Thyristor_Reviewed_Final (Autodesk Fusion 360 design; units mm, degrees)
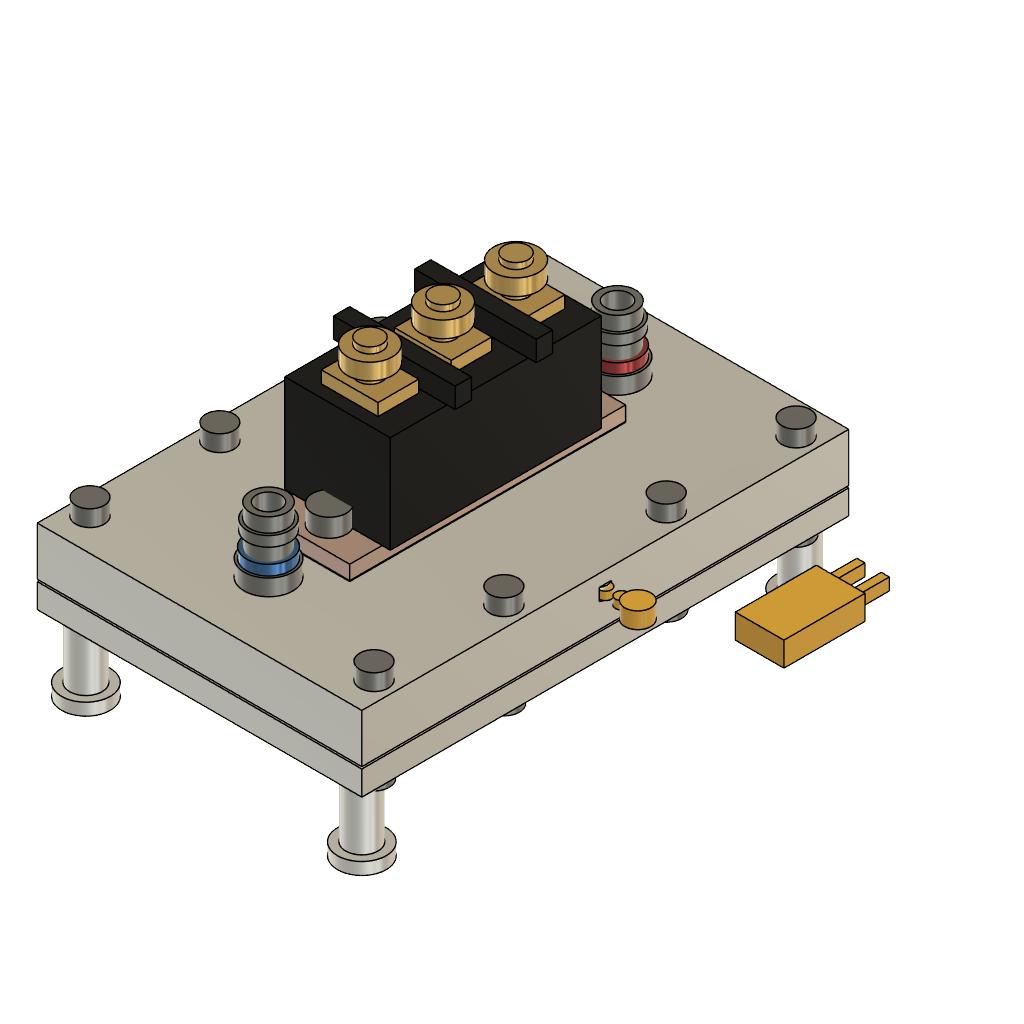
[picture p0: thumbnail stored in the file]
part number: 2026-11-02-01-28-30-721
part number: 2026-11-02-02-59-40-221
part number: 2026-11-02-02-59-43-084
part number: 2026-11-02-02-59-43-519
part number: 2026-11-02-02-59-44-128
part number: 2026-11-02-02-59-44-602
part number: 2026-11-02-02-59-44-987
part number: 2026-11-02-02-59-46-241
part number: 2026-11-02-02-59-47-034
part number: 2026-11-02-02-59-47-858
part number: 2026-11-02-02-59-48-789
part number: 2026-11-02-02-59-49-745
part number: 2026-11-02-02-59-54-096
part number: 2026-11-02-02-59-54-882
part number: 2026-11-02-02-59-56-951
part number: 2026-11-02-03-00-06-820
part number: 2026-11-02-03-00-18-161
part number: 2026-11-02-03-00-22-757
work_plane "WorkPlane1" AlongDistance 0 ExtraOffset 0
sketch "Cold plate stock sketch" plane through (0, 0, 0) normal (0, 0, 1) x axis (1, 0, 0)
  line L1 (80, 0) -> (0, 0)
  line L2 (80, 120) -> (80, 0)
  line L3 (0, 120) -> (80, 120)
  line L4 (0, 0) -> (0, 120)
extrude "Extrude1" new body sketch "Cold plate stock sketch" along normal blind 12
work_plane "WorkPlane2" AlongDistance 0 ExtraOffset 0
sketch "16 Mini-Channels | 2 x 5 x 70 mm sketch" plane through (0, 0, 0) normal (0, 0, 1) x axis (1, 0, 0)
  line L1 (14.75, 25) -> (12.75, 25)
  line L2 (14.75, 95) -> (14.75, 25)
  line L3 (12.75, 95) -> (14.75, 95)
  line L4 (12.75, 25) -> (12.75, 95)
  line L5 (18.25, 25) -> (16.25, 25)
  line L6 (18.25, 95) -> (18.25, 25)
  line L7 (16.25, 95) -> (18.25, 95)
  line L8 (16.25, 25) -> (16.25, 95)
  line L9 (21.75, 25) -> (19.75, 25)
  line L10 (21.75, 95) -> (21.75, 25)
  line L11 (19.75, 95) -> (21.75, 95)
  line L12 (19.75, 25) -> (19.75, 95)
  line L13 (25.25, 25) -> (23.25, 25)
  line L14 (25.25, 95) -> (25.25, 25)
  line L15 (23.25, 95) -> (25.25, 95)
  line L16 (23.25, 25) -> (23.25, 95)
  line L17 (28.75, 25) -> (26.75, 25)
  line L18 (28.75, 95) -> (28.75, 25)
  line L19 (26.75, 95) -> (28.75, 95)
  line L20 (26.75, 25) -> (26.75, 95)
  line L21 (32.25, 25) -> (30.25, 25)
  line L22 (32.25, 95) -> (32.25, 25)
  line L23 (30.25, 95) -> (32.25, 95)
  line L24 (30.25, 25) -> (30.25, 95)
  line L25 (35.75, 25) -> (33.75, 25)
  line L26 (35.75, 95) -> (35.75, 25)
  line L27 (33.75, 95) -> (35.75, 95)
  line L28 (33.75, 25) -> (33.75, 95)
  line L29 (39.25, 25) -> (37.25, 25)
  line L30 (39.25, 95) -> (39.25, 25)
  line L31 (37.25, 95) -> (39.25, 95)
  line L32 (37.25, 25) -> (37.25, 95)
  line L33 (42.75, 25) -> (40.75, 25)
  line L34 (42.75, 95) -> (42.75, 25)
  line L35 (40.75, 95) -> (42.75, 95)
  line L36 (40.75, 25) -> (40.75, 95)
  line L37 (46.25, 25) -> (44.25, 25)
  line L38 (46.25, 95) -> (46.25, 25)
  line L39 (44.25, 95) -> (46.25, 95)
  line L40 (44.25, 25) -> (44.25, 95)
  line L41 (49.75, 25) -> (47.75, 25)
  line L42 (49.75, 95) -> (49.75, 25)
  line L43 (47.75, 95) -> (49.75, 95)
  line L44 (47.75, 25) -> (47.75, 95)
  line L45 (53.25, 25) -> (51.25, 25)
  line L46 (53.25, 95) -> (53.25, 25)
  line L47 (51.25, 95) -> (53.25, 95)
  line L48 (51.25, 25) -> (51.25, 95)
  line L49 (56.75, 25) -> (54.75, 25)
  line L50 (56.75, 95) -> (56.75, 25)
  line L51 (54.75, 95) -> (56.75, 95)
  line L52 (54.75, 25) -> (54.75, 95)
  line L53 (60.25, 25) -> (58.25, 25)
  line L54 (60.25, 95) -> (60.25, 25)
  line L55 (58.25, 95) -> (60.25, 95)
  line L56 (58.25, 25) -> (58.25, 95)
  line L57 (63.75, 25) -> (61.75, 25)
  line L58 (63.75, 95) -> (63.75, 25)
  line L59 (61.75, 95) -> (63.75, 95)
  line L60 (61.75, 25) -> (61.75, 95)
  line L61 (67.25, 25) -> (65.25, 25)
  line L62 (67.25, 95) -> (67.25, 25)
  line L63 (65.25, 95) -> (67.25, 95)
  line L64 (65.25, 25) -> (65.25, 95)
extrude "Extrude2" cut sketch "16 Mini-Channels | 2 x 5 x 70 mm sketch" along normal blind 5
work_plane "WorkPlane3" AlongDistance 0 ExtraOffset 0
sketch "Headers sketch" plane through (0, 0, 0) normal (0, 0, 1) x axis (1, 0, 0)
  line L1 (70, 10) -> (10, 10)
  line L2 (70, 25) -> (70, 10)
  line L3 (10, 25) -> (70, 25)
  line L4 (10, 10) -> (10, 25)
  line L5 (70, 95) -> (10, 95)
  line L6 (70, 110) -> (70, 95)
  line L7 (10, 110) -> (70, 110)
  line L8 (10, 95) -> (10, 110)
extrude "Extrude3" cut sketch "Headers sketch" along normal blind 5
work_plane "WorkPlane4" AlongDistance 0 ExtraOffset 0
sketch "Boundary-layer breaks sketch" plane through (0, 0, 0) normal (0, 0, 1) x axis (1, 0, 0)
  line L1 (16.3, 42) -> (14.7, 42)
  line L2 (16.3, 44.5) -> (16.3, 42)
  line L3 (14.7, 44.5) -> (16.3, 44.5)
  line L4 (14.7, 42) -> (14.7, 44.5)
  line L5 (16.3, 68) -> (14.7, 68)
  line L6 (16.3, 70.5) -> (16.3, 68)
  line L7 (14.7, 70.5) -> (16.3, 70.5)
  line L8 (14.7, 68) -> (14.7, 70.5)
  line L9 (19.8, 52) -> (18.2, 52)
  line L10 (19.8, 54.5) -> (19.8, 52)
  line L11 (18.2, 54.5) -> (19.8, 54.5)
  line L12 (18.2, 52) -> (18.2, 54.5)
  line L13 (19.8, 78) -> (18.2, 78)
  line L14 (19.8, 80.5) -> (19.8, 78)
  line L15 (18.2, 80.5) -> (19.8, 80.5)
  line L16 (18.2, 78) -> (18.2, 80.5)
  line L17 (23.3, 42) -> (21.7, 42)
  line L18 (23.3, 44.5) -> (23.3, 42)
  line L19 (21.7, 44.5) -> (23.3, 44.5)
  line L20 (21.7, 42) -> (21.7, 44.5)
  line L21 (23.3, 68) -> (21.7, 68)
  line L22 (23.3, 70.5) -> (23.3, 68)
  line L23 (21.7, 70.5) -> (23.3, 70.5)
  line L24 (21.7, 68) -> (21.7, 70.5)
  line L25 (26.8, 52) -> (25.2, 52)
  line L26 (26.8, 54.5) -> (26.8, 52)
  line L27 (25.2, 54.5) -> (26.8, 54.5)
  line L28 (25.2, 52) -> (25.2, 54.5)
  line L29 (26.8, 78) -> (25.2, 78)
  line L30 (26.8, 80.5) -> (26.8, 78)
  line L31 (25.2, 80.5) -> (26.8, 80.5)
  line L32 (25.2, 78) -> (25.2, 80.5)
  line L33 (30.3, 42) -> (28.7, 42)
  line L34 (30.3, 44.5) -> (30.3, 42)
  line L35 (28.7, 44.5) -> (30.3, 44.5)
  line L36 (28.7, 42) -> (28.7, 44.5)
  line L37 (30.3, 68) -> (28.7, 68)
  line L38 (30.3, 70.5) -> (30.3, 68)
  line L39 (28.7, 70.5) -> (30.3, 70.5)
  line L40 (28.7, 68) -> (28.7, 70.5)
  line L41 (33.8, 52) -> (32.2, 52)
  line L42 (33.8, 54.5) -> (33.8, 52)
  line L43 (32.2, 54.5) -> (33.8, 54.5)
  line L44 (32.2, 52) -> (32.2, 54.5)
  line L45 (33.8, 78) -> (32.2, 78)
  line L46 (33.8, 80.5) -> (33.8, 78)
  line L47 (32.2, 80.5) -> (33.8, 80.5)
  line L48 (32.2, 78) -> (32.2, 80.5)
  line L49 (37.3, 42) -> (35.7, 42)
  line L50 (37.3, 44.5) -> (37.3, 42)
  line L51 (35.7, 44.5) -> (37.3, 44.5)
  line L52 (35.7, 42) -> (35.7, 44.5)
  line L53 (37.3, 68) -> (35.7, 68)
  line L54 (37.3, 70.5) -> (37.3, 68)
  line L55 (35.7, 70.5) -> (37.3, 70.5)
  line L56 (35.7, 68) -> (35.7, 70.5)
  line L57 (40.8, 52) -> (39.2, 52)
  line L58 (40.8, 54.5) -> (40.8, 52)
  line L59 (39.2, 54.5) -> (40.8, 54.5)
  line L60 (39.2, 52) -> (39.2, 54.5)
  line L61 (40.8, 78) -> (39.2, 78)
  line L62 (40.8, 80.5) -> (40.8, 78)
  line L63 (39.2, 80.5) -> (40.8, 80.5)
  line L64 (39.2, 78) -> (39.2, 80.5)
  line L65 (44.3, 42) -> (42.7, 42)
  line L66 (44.3, 44.5) -> (44.3, 42)
  line L67 (42.7, 44.5) -> (44.3, 44.5)
  line L68 (42.7, 42) -> (42.7, 44.5)
  line L69 (44.3, 68) -> (42.7, 68)
  line L70 (44.3, 70.5) -> (44.3, 68)
  line L71 (42.7, 70.5) -> (44.3, 70.5)
  line L72 (42.7, 68) -> (42.7, 70.5)
  line L73 (47.8, 52) -> (46.2, 52)
  line L74 (47.8, 54.5) -> (47.8, 52)
  line L75 (46.2, 54.5) -> (47.8, 54.5)
  line L76 (46.2, 52) -> (46.2, 54.5)
  line L77 (47.8, 78) -> (46.2, 78)
  line L78 (47.8, 80.5) -> (47.8, 78)
  line L79 (46.2, 80.5) -> (47.8, 80.5)
  line L80 (46.2, 78) -> (46.2, 80.5)
  line L81 (51.3, 42) -> (49.7, 42)
  line L82 (51.3, 44.5) -> (51.3, 42)
  line L83 (49.7, 44.5) -> (51.3, 44.5)
  line L84 (49.7, 42) -> (49.7, 44.5)
  line L85 (51.3, 68) -> (49.7, 68)
  line L86 (51.3, 70.5) -> (51.3, 68)
  line L87 (49.7, 70.5) -> (51.3, 70.5)
  line L88 (49.7, 68) -> (49.7, 70.5)
  line L89 (54.8, 52) -> (53.2, 52)
  line L90 (54.8, 54.5) -> (54.8, 52)
  line L91 (53.2, 54.5) -> (54.8, 54.5)
  line L92 (53.2, 52) -> (53.2, 54.5)
  line L93 (54.8, 78) -> (53.2, 78)
  line L94 (54.8, 80.5) -> (54.8, 78)
  line L95 (53.2, 80.5) -> (54.8, 80.5)
  line L96 (53.2, 78) -> (53.2, 80.5)
  line L97 (58.3, 42) -> (56.7, 42)
  line L98 (58.3, 44.5) -> (58.3, 42)
  line L99 (56.7, 44.5) -> (58.3, 44.5)
  line L100 (56.7, 42) -> (56.7, 44.5)
  line L101 (58.3, 68) -> (56.7, 68)
  line L102 (58.3, 70.5) -> (58.3, 68)
  line L103 (56.7, 70.5) -> (58.3, 70.5)
  line L104 (56.7, 68) -> (56.7, 70.5)
  line L105 (61.8, 52) -> (60.2, 52)
  line L106 (61.8, 54.5) -> (61.8, 52)
  line L107 (60.2, 54.5) -> (61.8, 54.5)
  line L108 (60.2, 52) -> (60.2, 54.5)
  line L109 (61.8, 78) -> (60.2, 78)
  line L110 (61.8, 80.5) -> (61.8, 78)
  line L111 (60.2, 80.5) -> (61.8, 80.5)
  line L112 (60.2, 78) -> (60.2, 80.5)
  line L113 (65.3, 42) -> (63.7, 42)
  line L114 (65.3, 44.5) -> (65.3, 42)
  line L115 (63.7, 44.5) -> (65.3, 44.5)
  line L116 (63.7, 42) -> (63.7, 44.5)
  line L117 (65.3, 68) -> (63.7, 68)
  line L118 (65.3, 70.5) -> (65.3, 68)
  line L119 (63.7, 70.5) -> (65.3, 70.5)
  line L120 (63.7, 68) -> (63.7, 70.5)
extrude "Extrude4" cut sketch "Boundary-layer breaks sketch" along normal blind 5
work_plane "WorkPlane5" AlongDistance 0 ExtraOffset 0
sketch "Gasket groove 1 sketch" plane through (0, 0, 0) normal (0, 0, 1) x axis (1, 0, 0)
  line L1 (73, 7) -> (7, 7)
  line L2 (73, 9) -> (73, 7)
  line L3 (7, 9) -> (73, 9)
  line L4 (7, 7) -> (7, 9)
extrude "Extrude5" cut sketch "Gasket groove 1 sketch" along normal blind 0.5
work_plane "WorkPlane6" AlongDistance 0 ExtraOffset 0
sketch "Gasket groove 2 sketch" plane through (0, 0, 0) normal (0, 0, 1) x axis (1, 0, 0)
  line L1 (73, 111) -> (7, 111)
  line L2 (73, 113) -> (73, 111)
  line L3 (7, 113) -> (73, 113)
  line L4 (7, 111) -> (7, 113)
extrude "Extrude6" cut sketch "Gasket groove 2 sketch" along normal blind 0.5
work_plane "WorkPlane7" AlongDistance 0 ExtraOffset 0
sketch "Gasket groove 3 sketch" plane through (0, 0, 0) normal (0, 0, 1) x axis (1, 0, 0)
  line L1 (9, 9) -> (7, 9)
  line L2 (9, 111) -> (9, 9)
  line L3 (7, 111) -> (9, 111)
  line L4 (7, 9) -> (7, 111)
extrude "Extrude7" cut sketch "Gasket groove 3 sketch" along normal blind 0.5
work_plane "WorkPlane8" AlongDistance 0 ExtraOffset 0
sketch "Gasket groove 4 sketch" plane through (0, 0, 0) normal (0, 0, 1) x axis (1, 0, 0)
  line L1 (73, 9) -> (71, 9)
  line L2 (73, 111) -> (73, 9)
  line L3 (71, 111) -> (73, 111)
  line L4 (71, 9) -> (71, 111)
extrude "Extrude8" cut sketch "Gasket groove 4 sketch" along normal blind 0.5
work_plane "WorkPlane9" AlongDistance 12 ExtraOffset 0
sketch "Fluid port through-bores sketch" plane through (0, 0, 12) normal (0, 0, 1) x axis (1, 0, 0)
  circle C1 centre (40, 17) radius 3
  circle C2 centre (40, 103) radius 3
extrude "Extrude9" cut sketch "Fluid port through-bores sketch" against normal blind 7 (magnitude of "-( 7 mm )")
work_plane "WorkPlane10" AlongDistance 12 ExtraOffset 0
sketch "Cover bolt holes sketch" plane through (0, 0, 12) normal (0, 0, 1) x axis (1, 0, 0)
  circle C1 centre (5, 8) radius 2.2
  circle C2 centre (75, 8) radius 2.2
  circle C3 centre (5, 40) radius 2.2
  circle C4 centre (75, 40) radius 2.2
  circle C5 centre (5, 80) radius 2.2
  circle C6 centre (75, 80) radius 2.2
  circle C7 centre (5, 112) radius 2.2
  circle C8 centre (75, 112) radius 2.2
extrude "Extrude10" cut sketch "Cover bolt holes sketch" against normal blind 12 (magnitude of "-( 12 mm )")
work_plane "WorkPlane11" AlongDistance 12 ExtraOffset 0
sketch "SCR M5 tapped holes sketch" plane through (0, 0, 12) normal (0, 0, 1) x axis (1, 0, 0)
  circle C1 centre (40, 32) radius 2.1
  circle C2 centre (40, 88) radius 2.1
extrude "Extrude11" cut sketch "SCR M5 tapped holes sketch" along normal blind 4
work_plane "WorkPlane12" AlongDistance 6 ExtraOffset 0
sketch "Thermowell entry boss sketch" plane through (0, 0, 6) normal (0, 0, 1) x axis (1, 0, 0)
  circle C1 centre (78, 60) radius 2.5
extrude "Extrude12" add sketch "Thermowell entry boss sketch" along normal blind 3
work_plane "WorkPlane1" AlongDistance 0 ExtraOffset 0
sketch "Gasket blank sketch" plane through (0, 0, 0) normal (0, 0, 1) x axis (1, 0, 0)
  line L1 (73, 7) -> (7, 7)
  line L2 (73, 113) -> (73, 7)
  line L3 (7, 113) -> (73, 113)
  line L4 (7, 7) -> (7, 113)
extrude "Extrude1" new body sketch "Gasket blank sketch" against normal blind 0.5 (magnitude of "-( 0.5 mm )")
work_plane "WorkPlane2" AlongDistance 0 ExtraOffset 0
sketch "Gasket fluid aperture sketch" plane through (0, 0, 0) normal (0, 0, 1) x axis (1, 0, 0)
  line L1 (71, 9) -> (9, 9)
  line L2 (71, 111) -> (71, 9)
  line L3 (9, 111) -> (71, 111)
  line L4 (9, 9) -> (9, 111)
extrude "Extrude2" cut sketch "Gasket fluid aperture sketch" against normal blind 0.5 (magnitude of "-( 0.5 mm )")
work_plane "WorkPlane1" AlongDistance -0.5 ExtraOffset 0
sketch "Bottom cover slab sketch" plane through (0, 0, -0.5) normal (0, 0, 1) x axis (1, 0, 0)
  line L1 (80, 0) -> (0, 0)
  line L2 (80, 120) -> (80, 0)
  line L3 (0, 120) -> (80, 120)
  line L4 (0, 0) -> (0, 120)
extrude "Extrude1" new body sketch "Bottom cover slab sketch" against normal blind 6 (magnitude of "-( 6.0 mm )")
work_plane "WorkPlane2" AlongDistance -0.5 ExtraOffset 0
sketch "Cover bolt holes sketch" plane through (0, 0, -0.5) normal (0, 0, 1) x axis (1, 0, 0)
  circle C1 centre (5, 8) radius 2.2
  circle C2 centre (75, 8) radius 2.2
  circle C3 centre (5, 40) radius 2.2
  circle C4 centre (75, 40) radius 2.2
  circle C5 centre (5, 80) radius 2.2
  circle C6 centre (75, 80) radius 2.2
  circle C7 centre (5, 112) radius 2.2
  circle C8 centre (75, 112) radius 2.2
extrude "Extrude2" cut sketch "Cover bolt holes sketch" against normal blind 6 (magnitude of "-( 6.0 mm )")
work_plane "WorkPlane1" AlongDistance 12 ExtraOffset 0
sketch "Hex collar sketch" plane through (0, 0, 12) normal (0, 0, 1) x axis (1, 0, 0)
  circle C1 centre (40, 17) radius 6
extrude "Extrude1" new body sketch "Hex collar sketch" along normal blind 4
work_plane "WorkPlane2" AlongDistance 16 ExtraOffset 0
sketch "Barb stem sketch" plane through (0, 0, 16) normal (0, 0, 1) x axis (1, 0, 0)
  circle C1 centre (40, 17) radius 4.5
extrude "Extrude2" add sketch "Barb stem sketch" along normal blind 12
work_plane "WorkPlane3" AlongDistance 22 ExtraOffset 0
sketch "Retention barb bead sketch" plane through (0, 0, 22) normal (0, 0, 1) x axis (1, 0, 0)
  circle C1 centre (40, 17) radius 5.2
extrude "Extrude3" add sketch "Retention barb bead sketch" along normal blind 2.5
work_plane "WorkPlane4" AlongDistance 28 ExtraOffset 0
sketch "Continuous fluid bore sketch" plane through (0, 0, 28) normal (0, 0, 1) x axis (1, 0, 0)
  circle C1 centre (40, 17) radius 3
extrude "Extrude4" cut sketch "Continuous fluid bore sketch" against normal blind 16 (magnitude of "-( 16.0 mm )")
work_plane "WorkPlane1" AlongDistance 16 ExtraOffset 0
sketch "Identifier ring sketch" plane through (0, 0, 16) normal (0, 0, 1) x axis (1, 0, 0)
  circle C1 centre (40, 17) radius 5.4
extrude "Extrude1" new body sketch "Identifier ring sketch" along normal blind 2.5
work_plane "WorkPlane2" AlongDistance 16 ExtraOffset 0
sketch "Ring bore sketch" plane through (0, 0, 16) normal (0, 0, 1) x axis (1, 0, 0)
  circle C1 centre (40, 17) radius 4.5
extrude "Extrude5" cut sketch "Ring bore sketch" along normal blind 2.5
work_plane "WorkPlane1" AlongDistance 12 ExtraOffset 0
sketch "Hex collar sketch" plane through (0, 0, 12) normal (0, 0, 1) x axis (1, 0, 0)
  circle C1 centre (40, 103) radius 6
extrude "Extrude1" new body sketch "Hex collar sketch" along normal blind 4
work_plane "WorkPlane2" AlongDistance 16 ExtraOffset 0
sketch "Barb stem sketch" plane through (0, 0, 16) normal (0, 0, 1) x axis (1, 0, 0)
  circle C1 centre (40, 103) radius 4.5
extrude "Extrude2" add sketch "Barb stem sketch" along normal blind 12
work_plane "WorkPlane3" AlongDistance 22 ExtraOffset 0
sketch "Retention barb bead sketch" plane through (0, 0, 22) normal (0, 0, 1) x axis (1, 0, 0)
  circle C1 centre (40, 103) radius 5.2
extrude "Extrude3" add sketch "Retention barb bead sketch" along normal blind 2.5
work_plane "WorkPlane4" AlongDistance 28 ExtraOffset 0
sketch "Continuous fluid bore sketch" plane through (0, 0, 28) normal (0, 0, 1) x axis (1, 0, 0)
  circle C1 centre (40, 103) radius 3
extrude "Extrude4" cut sketch "Continuous fluid bore sketch" against normal blind 16 (magnitude of "-( 16.0 mm )")
work_plane "WorkPlane1" AlongDistance 16 ExtraOffset 0
sketch "Identifier ring sketch" plane through (0, 0, 16) normal (0, 0, 1) x axis (1, 0, 0)
  circle C1 centre (40, 103) radius 5.4
extrude "Extrude1" new body sketch "Identifier ring sketch" along normal blind 2.5
work_plane "WorkPlane2" AlongDistance 16 ExtraOffset 0
sketch "Ring bore sketch" plane through (0, 0, 16) normal (0, 0, 1) x axis (1, 0, 0)
  circle C1 centre (40, 103) radius 4.5
extrude "Extrude5" cut sketch "Ring bore sketch" along normal blind 2.5
work_plane "WorkPlane1" AlongDistance 12 ExtraOffset 0
sketch "TIM envelope sketch" plane through (0, 0, 12) normal (0, 0, 1) x axis (1, 0, 0)
  line L1 (51, 26) -> (29, 26)
  line L2 (51, 94) -> (51, 26)
  line L3 (29, 94) -> (51, 94)
  line L4 (29, 26) -> (29, 94)
extrude "Extrude1" new body sketch "TIM envelope sketch" along normal blind 0.2
work_plane "WorkPlane2" AlongDistance 12 ExtraOffset 0
sketch "TIM bolt clearance sketch" plane through (0, 0, 12) normal (0, 0, 1) x axis (1, 0, 0)
  circle C1 centre (40, 32) radius 2.5
  circle C2 centre (40, 88) radius 2.5
extrude "Extrude2" cut sketch "TIM bolt clearance sketch" along normal blind 0.2
work_plane "WorkPlane1" AlongDistance 12.2 ExtraOffset 0
sketch "Copper baseplate sketch" plane through (0, 0, 12.2) normal (0, 0, 1) x axis (1, 0, 0)
  line L1 (51, 26) -> (29, 26)
  line L2 (51, 94) -> (51, 26)
  line L3 (29, 94) -> (51, 94)
  line L4 (29, 26) -> (29, 94)
extrude "Extrude1" new body sketch "Copper baseplate sketch" along normal blind 3.5
work_plane "WorkPlane2" AlongDistance 12.2 ExtraOffset 0
sketch "U-bolt mounting slots sketch" plane through (0, 0, 12.2) normal (0, 0, 1) x axis (1, 0, 0)
  circle C1 centre (40, 32) radius 2.6
  circle C2 centre (40, 88) radius 2.6
extrude "Extrude2" cut sketch "U-bolt mounting slots sketch" along normal blind 3.5
work_plane "WorkPlane1" AlongDistance 15.7 ExtraOffset 0
sketch "SCR plastic body sketch" plane through (0, 0, 15.7) normal (0, 0, 1) x axis (1, 0, 0)
  line L1 (53, 34) -> (27, 34)
  line L2 (53, 86) -> (53, 34)
  line L3 (27, 86) -> (53, 86)
  line L4 (27, 34) -> (27, 86)
extrude "Extrude1" new body sketch "SCR plastic body sketch" along normal blind 24
work_plane "WorkPlane2" AlongDistance 39.7 ExtraOffset 0
sketch "Phase isolation barriers sketch" plane through (0, 0, 39.7) normal (0, 0, 1) x axis (1, 0, 0)
  line L1 (55, 48) -> (25, 48)
  line L2 (55, 52) -> (55, 48)
  line L3 (25, 52) -> (55, 52)
  line L4 (25, 48) -> (25, 52)
  line L5 (55, 68) -> (25, 68)
  line L6 (55, 72) -> (55, 68)
  line L7 (25, 72) -> (55, 72)
  line L8 (25, 68) -> (25, 72)
extrude "Extrude2" add sketch "Phase isolation barriers sketch" along normal blind 5
work_plane "WorkPlane1" AlongDistance 39.7 ExtraOffset 0
sketch "Pad_42.0 sketch" plane through (0, 0, 39.7) normal (0, 0, 1) x axis (1, 0, 0)
  line L1 (47, 37) -> (33, 37)
  line L2 (47, 47) -> (47, 37)
  line L3 (33, 47) -> (47, 47)
  line L4 (33, 37) -> (33, 47)
extrude "Extrude1" new body sketch "Pad_42.0 sketch" along normal blind 3
work_plane "WorkPlane2" AlongDistance 42.7 ExtraOffset 0
sketch "Stud_42.0 sketch" plane through (0, 0, 42.7) normal (0, 0, 1) x axis (1, 0, 0)
  circle C1 centre (40, 42) radius 3
extrude "Extrude2" add sketch "Stud_42.0 sketch" along normal blind 8
work_plane "WorkPlane3" AlongDistance 45.2 ExtraOffset 0
sketch "Nut_42.0 sketch" plane through (0, 0, 45.2) normal (0, 0, 1) x axis (1, 0, 0)
  circle C1 centre (40, 42) radius 5.5
extrude "Extrude3" add sketch "Nut_42.0 sketch" along normal blind 4
work_plane "WorkPlane4" AlongDistance 39.7 ExtraOffset 0
sketch "Pad_60.0 sketch" plane through (0, 0, 39.7) normal (0, 0, 1) x axis (1, 0, 0)
  line L1 (47, 55) -> (33, 55)
  line L2 (47, 65) -> (47, 55)
  line L3 (33, 65) -> (47, 65)
  line L4 (33, 55) -> (33, 65)
extrude "Extrude4" new body sketch "Pad_60.0 sketch" along normal blind 3
work_plane "WorkPlane5" AlongDistance 42.7 ExtraOffset 0
sketch "Stud_60.0 sketch" plane through (0, 0, 42.7) normal (0, 0, 1) x axis (1, 0, 0)
  circle C1 centre (40, 60) radius 3
extrude "Extrude5" add sketch "Stud_60.0 sketch" along normal blind 8
work_plane "WorkPlane6" AlongDistance 45.2 ExtraOffset 0
sketch "Nut_60.0 sketch" plane through (0, 0, 45.2) normal (0, 0, 1) x axis (1, 0, 0)
  circle C1 centre (40, 60) radius 5.5
extrude "Extrude6" add sketch "Nut_60.0 sketch" along normal blind 4
work_plane "WorkPlane7" AlongDistance 39.7 ExtraOffset 0
sketch "Pad_78.0 sketch" plane through (0, 0, 39.7) normal (0, 0, 1) x axis (1, 0, 0)
  line L1 (47, 73) -> (33, 73)
  line L2 (47, 83) -> (47, 73)
  line L3 (33, 83) -> (47, 83)
  line L4 (33, 73) -> (33, 83)
extrude "Extrude7" new body sketch "Pad_78.0 sketch" along normal blind 3
work_plane "WorkPlane8" AlongDistance 42.7 ExtraOffset 0
sketch "Stud_78.0 sketch" plane through (0, 0, 42.7) normal (0, 0, 1) x axis (1, 0, 0)
  circle C1 centre (40, 78) radius 3
extrude "Extrude8" add sketch "Stud_78.0 sketch" along normal blind 8
work_plane "WorkPlane9" AlongDistance 45.2 ExtraOffset 0
sketch "Nut_78.0 sketch" plane through (0, 0, 45.2) normal (0, 0, 1) x axis (1, 0, 0)
  circle C1 centre (40, 78) radius 5.5
extrude "Extrude9" add sketch "Nut_78.0 sketch" along normal blind 4
work_plane "WorkPlane1" AlongDistance 26 ExtraOffset 0
sketch "Gate pins sketch" plane through (0, 0, 26) normal (0, 0, 1) x axis (1, 0, 0)
  line L1 (27.5, 56) -> (26, 56)
  line L2 (27.5, 58.5) -> (27.5, 56)
  line L3 (26, 58.5) -> (27.5, 58.5)
  line L4 (26, 56) -> (26, 58.5)
  line L5 (27.5, 61.5) -> (26, 61.5)
  line L6 (27.5, 64) -> (27.5, 61.5)
  line L7 (26, 64) -> (27.5, 64)
  line L8 (26, 61.5) -> (26, 64)
extrude "Extrude1" new body sketch "Gate pins sketch" along normal blind 6
work_plane "WorkPlane1" AlongDistance 15.7 ExtraOffset 0
sketch "Head_32.0 sketch" plane through (0, 0, 15.7) normal (0, 0, 1) x axis (1, 0, 0)
  circle C1 centre (40, 32) radius 4.2
extrude "Extrude1" new body sketch "Head_32.0 sketch" along normal blind 4.5
work_plane "WorkPlane2" AlongDistance 15.7 ExtraOffset 0
sketch "Shank_32.0 sketch" plane through (0, 0, 15.7) normal (0, 0, 1) x axis (1, 0, 0)
  circle C1 centre (40, 32) radius 2.4
extrude "Extrude2" add sketch "Shank_32.0 sketch" against normal blind 7
work_plane "WorkPlane3" AlongDistance 15.7 ExtraOffset 0
sketch "Head_88.0 sketch" plane through (0, 0, 15.7) normal (0, 0, 1) x axis (1, 0, 0)
  circle C1 centre (40, 88) radius 4.2
extrude "Extrude3" new body sketch "Head_88.0 sketch" along normal blind 4.5
work_plane "WorkPlane4" AlongDistance 15.7 ExtraOffset 0
sketch "Shank_88.0 sketch" plane through (0, 0, 15.7) normal (0, 0, 1) x axis (1, 0, 0)
  circle C1 centre (40, 88) radius 2.4
extrude "Extrude4" add sketch "Shank_88.0 sketch" against normal blind 7
work_plane "WorkPlane1" AlongDistance 12 ExtraOffset 0
sketch "BHead_5_8 sketch" plane through (0, 0, 12) normal (0, 0, 1) x axis (1, 0, 0)
  circle C1 centre (5, 8) radius 3.5
extrude "Extrude1" new body sketch "BHead_5_8 sketch" along normal blind 4
work_plane "WorkPlane2" AlongDistance 12 ExtraOffset 0
sketch "BShank_5_8 sketch" plane through (0, 0, 12) normal (0, 0, 1) x axis (1, 0, 0)
  circle C1 centre (5, 8) radius 1.9
extrude "Extrude2" add sketch "BShank_5_8 sketch" against normal blind 22
work_plane "WorkPlane3" AlongDistance 12 ExtraOffset 0
sketch "BHead_75_8 sketch" plane through (0, 0, 12) normal (0, 0, 1) x axis (1, 0, 0)
  circle C1 centre (75, 8) radius 3.5
extrude "Extrude3" new body sketch "BHead_75_8 sketch" along normal blind 4
work_plane "WorkPlane4" AlongDistance 12 ExtraOffset 0
sketch "BShank_75_8 sketch" plane through (0, 0, 12) normal (0, 0, 1) x axis (1, 0, 0)
  circle C1 centre (75, 8) radius 1.9
extrude "Extrude4" add sketch "BShank_75_8 sketch" against normal blind 22
work_plane "WorkPlane5" AlongDistance 12 ExtraOffset 0
sketch "BHead_5_40 sketch" plane through (0, 0, 12) normal (0, 0, 1) x axis (1, 0, 0)
  circle C1 centre (5, 40) radius 3.5
extrude "Extrude5" new body sketch "BHead_5_40 sketch" along normal blind 4
work_plane "WorkPlane6" AlongDistance 12 ExtraOffset 0
sketch "BShank_5_40 sketch" plane through (0, 0, 12) normal (0, 0, 1) x axis (1, 0, 0)
  circle C1 centre (5, 40) radius 1.9
extrude "Extrude6" add sketch "BShank_5_40 sketch" against normal blind 22
work_plane "WorkPlane7" AlongDistance 12 ExtraOffset 0
sketch "BHead_75_40 sketch" plane through (0, 0, 12) normal (0, 0, 1) x axis (1, 0, 0)
  circle C1 centre (75, 40) radius 3.5
extrude "Extrude7" new body sketch "BHead_75_40 sketch" along normal blind 4
work_plane "WorkPlane8" AlongDistance 12 ExtraOffset 0
sketch "BShank_75_40 sketch" plane through (0, 0, 12) normal (0, 0, 1) x axis (1, 0, 0)
  circle C1 centre (75, 40) radius 1.9
extrude "Extrude8" add sketch "BShank_75_40 sketch" against normal blind 22
work_plane "WorkPlane9" AlongDistance 12 ExtraOffset 0
sketch "BHead_5_80 sketch" plane through (0, 0, 12) normal (0, 0, 1) x axis (1, 0, 0)
  circle C1 centre (5, 80) radius 3.5
extrude "Extrude9" new body sketch "BHead_5_80 sketch" along normal blind 4
work_plane "WorkPlane10" AlongDistance 12 ExtraOffset 0
sketch "BShank_5_80 sketch" plane through (0, 0, 12) normal (0, 0, 1) x axis (1, 0, 0)
  circle C1 centre (5, 80) radius 1.9
extrude "Extrude10" add sketch "BShank_5_80 sketch" against normal blind 22
work_plane "WorkPlane11" AlongDistance 12 ExtraOffset 0
sketch "BHead_75_80 sketch" plane through (0, 0, 12) normal (0, 0, 1) x axis (1, 0, 0)
  circle C1 centre (75, 80) radius 3.5
extrude "Extrude11" new body sketch "BHead_75_80 sketch" along normal blind 4
work_plane "WorkPlane12" AlongDistance 12 ExtraOffset 0
sketch "BShank_75_80 sketch" plane through (0, 0, 12) normal (0, 0, 1) x axis (1, 0, 0)
  circle C1 centre (75, 80) radius 1.9
extrude "Extrude12" add sketch "BShank_75_80 sketch" against normal blind 22
work_plane "WorkPlane13" AlongDistance 12 ExtraOffset 0
sketch "BHead_5_112 sketch" plane through (0, 0, 12) normal (0, 0, 1) x axis (1, 0, 0)
  circle C1 centre (5, 112) radius 3.5
extrude "Extrude13" new body sketch "BHead_5_112 sketch" along normal blind 4
work_plane "WorkPlane14" AlongDistance 12 ExtraOffset 0
sketch "BShank_5_112 sketch" plane through (0, 0, 12) normal (0, 0, 1) x axis (1, 0, 0)
  circle C1 centre (5, 112) radius 1.9
extrude "Extrude14" add sketch "BShank_5_112 sketch" against normal blind 22
work_plane "WorkPlane15" AlongDistance 12 ExtraOffset 0
sketch "BHead_75_112 sketch" plane through (0, 0, 12) normal (0, 0, 1) x axis (1, 0, 0)
  circle C1 centre (75, 112) radius 3.5
extrude "Extrude15" new body sketch "BHead_75_112 sketch" along normal blind 4
work_plane "WorkPlane16" AlongDistance 12 ExtraOffset 0
sketch "BShank_75_112 sketch" plane through (0, 0, 12) normal (0, 0, 1) x axis (1, 0, 0)
  circle C1 centre (75, 112) radius 1.9
extrude "Extrude16" add sketch "BShank_75_112 sketch" against normal blind 22
work_plane "WorkPlane1" AlongDistance -6.5 ExtraOffset 0
sketch "Nut_5_8 sketch" plane through (0, 0, -6.5) normal (0, 0, 1) x axis (1, 0, 0)
  circle C1 centre (5, 8) radius 3.8
extrude "Extrude1" new body sketch "Nut_5_8 sketch" against normal blind 3 (magnitude of "-( 3.0 mm )")
work_plane "WorkPlane2" AlongDistance -6.5 ExtraOffset 0
sketch "NutBore_5_8 sketch" plane through (0, 0, -6.5) normal (0, 0, 1) x axis (1, 0, 0)
  circle C1 centre (5, 8) radius 2
extrude "Extrude2" cut sketch "NutBore_5_8 sketch" against normal blind 3 (magnitude of "-( 3.0 mm )")
work_plane "WorkPlane3" AlongDistance -6.5 ExtraOffset 0
sketch "Nut_75_8 sketch" plane through (0, 0, -6.5) normal (0, 0, 1) x axis (1, 0, 0)
  circle C1 centre (75, 8) radius 3.8
extrude "Extrude3" new body sketch "Nut_75_8 sketch" against normal blind 3 (magnitude of "-( 3.0 mm )")
work_plane "WorkPlane4" AlongDistance -6.5 ExtraOffset 0
sketch "NutBore_75_8 sketch" plane through (0, 0, -6.5) normal (0, 0, 1) x axis (1, 0, 0)
  circle C1 centre (75, 8) radius 2
extrude "Extrude4" cut sketch "NutBore_75_8 sketch" against normal blind 3 (magnitude of "-( 3.0 mm )")
work_plane "WorkPlane5" AlongDistance -6.5 ExtraOffset 0
sketch "Nut_5_40 sketch" plane through (0, 0, -6.5) normal (0, 0, 1) x axis (1, 0, 0)
  circle C1 centre (5, 40) radius 3.8
extrude "Extrude5" new body sketch "Nut_5_40 sketch" against normal blind 3 (magnitude of "-( 3.0 mm )")
work_plane "WorkPlane6" AlongDistance -6.5 ExtraOffset 0
sketch "NutBore_5_40 sketch" plane through (0, 0, -6.5) normal (0, 0, 1) x axis (1, 0, 0)
  circle C1 centre (5, 40) radius 2
extrude "Extrude6" cut sketch "NutBore_5_40 sketch" against normal blind 3 (magnitude of "-( 3.0 mm )")
work_plane "WorkPlane7" AlongDistance -6.5 ExtraOffset 0
sketch "Nut_75_40 sketch" plane through (0, 0, -6.5) normal (0, 0, 1) x axis (1, 0, 0)
  circle C1 centre (75, 40) radius 3.8
extrude "Extrude7" new body sketch "Nut_75_40 sketch" against normal blind 3 (magnitude of "-( 3.0 mm )")
work_plane "WorkPlane8" AlongDistance -6.5 ExtraOffset 0
sketch "NutBore_75_40 sketch" plane through (0, 0, -6.5) normal (0, 0, 1) x axis (1, 0, 0)
  circle C1 centre (75, 40) radius 2
extrude "Extrude8" cut sketch "NutBore_75_40 sketch" against normal blind 3 (magnitude of "-( 3.0 mm )")
work_plane "WorkPlane9" AlongDistance -6.5 ExtraOffset 0
sketch "Nut_5_80 sketch" plane through (0, 0, -6.5) normal (0, 0, 1) x axis (1, 0, 0)
  circle C1 centre (5, 80) radius 3.8
extrude "Extrude9" new body sketch "Nut_5_80 sketch" against normal blind 3 (magnitude of "-( 3.0 mm )")
work_plane "WorkPlane10" AlongDistance -6.5 ExtraOffset 0
sketch "NutBore_5_80 sketch" plane through (0, 0, -6.5) normal (0, 0, 1) x axis (1, 0, 0)
  circle C1 centre (5, 80) radius 2
extrude "Extrude10" cut sketch "NutBore_5_80 sketch" against normal blind 3 (magnitude of "-( 3.0 mm )")
work_plane "WorkPlane11" AlongDistance -6.5 ExtraOffset 0
sketch "Nut_75_80 sketch" plane through (0, 0, -6.5) normal (0, 0, 1) x axis (1, 0, 0)
  circle C1 centre (75, 80) radius 3.8
extrude "Extrude11" new body sketch "Nut_75_80 sketch" against normal blind 3 (magnitude of "-( 3.0 mm )")
work_plane "WorkPlane12" AlongDistance -6.5 ExtraOffset 0
sketch "NutBore_75_80 sketch" plane through (0, 0, -6.5) normal (0, 0, 1) x axis (1, 0, 0)
  circle C1 centre (75, 80) radius 2
extrude "Extrude12" cut sketch "NutBore_75_80 sketch" against normal blind 3 (magnitude of "-( 3.0 mm )")
work_plane "WorkPlane13" AlongDistance -6.5 ExtraOffset 0
sketch "Nut_5_112 sketch" plane through (0, 0, -6.5) normal (0, 0, 1) x axis (1, 0, 0)
  circle C1 centre (5, 112) radius 3.8
extrude "Extrude13" new body sketch "Nut_5_112 sketch" against normal blind 3 (magnitude of "-( 3.0 mm )")
work_plane "WorkPlane14" AlongDistance -6.5 ExtraOffset 0
sketch "NutBore_5_112 sketch" plane through (0, 0, -6.5) normal (0, 0, 1) x axis (1, 0, 0)
  circle C1 centre (5, 112) radius 2
extrude "Extrude14" cut sketch "NutBore_5_112 sketch" against normal blind 3 (magnitude of "-( 3.0 mm )")
work_plane "WorkPlane15" AlongDistance -6.5 ExtraOffset 0
sketch "Nut_75_112 sketch" plane through (0, 0, -6.5) normal (0, 0, 1) x axis (1, 0, 0)
  circle C1 centre (75, 112) radius 3.8
extrude "Extrude15" new body sketch "Nut_75_112 sketch" against normal blind 3 (magnitude of "-( 3.0 mm )")
work_plane "WorkPlane16" AlongDistance -6.5 ExtraOffset 0
sketch "NutBore_75_112 sketch" plane through (0, 0, -6.5) normal (0, 0, 1) x axis (1, 0, 0)
  circle C1 centre (75, 112) radius 2
extrude "Extrude16" cut sketch "NutBore_75_112 sketch" against normal blind 3 (magnitude of "-( 3.0 mm )")
work_plane "WorkPlane1" AlongDistance 6.5 ExtraOffset 0
sketch "Sensor probe in thermowell sketch" plane through (0, 0, 6.5) normal (0, 0, 1) x axis (1, 0, 0)
  circle C1 centre (80, 60) radius 1.5
extrude "Extrude1" new body sketch "Sensor probe in thermowell sketch" along normal blind 2
work_plane "WorkPlane2" AlongDistance 6.5 ExtraOffset 0
sketch "Probe sheath sketch" plane through (0, 0, 6.5) normal (0, 0, 1) x axis (1, 0, 0)
  circle C1 centre (84, 60) radius 1.5
extrude "Extrude2" new body sketch "Probe sheath sketch" along normal blind 2
work_plane "WorkPlane3" AlongDistance 5.5 ExtraOffset 0
sketch "Brass compression gland sketch" plane through (0, 0, 5.5) normal (0, 0, 1) x axis (1, 0, 0)
  circle C1 centre (88, 60) radius 3.2
extrude "Extrude3" add sketch "Brass compression gland sketch" along normal blind 4
work_plane "WorkPlane4" AlongDistance 3 ExtraOffset 0
sketch "Yellow connector plug sketch" plane through (0, 0, 3) normal (0, 0, 1) x axis (1, 0, 0)
  line L1 (114, 70) -> (102, 70)
  line L2 (114, 90) -> (114, 70)
  line L3 (102, 90) -> (114, 90)
  line L4 (102, 70) -> (102, 90)
extrude "Extrude4" new body sketch "Yellow connector plug sketch" along normal blind 6
work_plane "WorkPlane5" AlongDistance 4.5 ExtraOffset 0
sketch "Spade prongs sketch" plane through (0, 0, 4.5) normal (0, 0, 1) x axis (1, 0, 0)
  line L1 (106, 90) -> (104, 90)
  line L2 (106, 98) -> (106, 90)
  line L3 (104, 98) -> (106, 98)
  line L4 (104, 90) -> (104, 98)
  line L5 (112, 90) -> (110, 90)
  line L6 (112, 98) -> (112, 90)
  line L7 (110, 98) -> (112, 98)
  line L8 (110, 90) -> (110, 98)
extrude "Extrude5" add sketch "Spade prongs sketch" along normal blind 3
work_plane "WorkPlane1" AlongDistance -6.5 ExtraOffset 0
sketch "Leg_6_6 sketch" plane through (0, 0, -6.5) normal (0, 0, 1) x axis (1, 0, 0)
  circle C1 centre (6, 6) radius 4
extrude "Extrude1" new body sketch "Leg_6_6 sketch" against normal blind 16 (magnitude of "-( 16.0 mm )")
work_plane "WorkPlane2" AlongDistance -22.5 ExtraOffset 0
sketch "Foot_6_6 sketch" plane through (0, 0, -22.5) normal (0, 0, 1) x axis (1, 0, 0)
  circle C1 centre (6, 6) radius 6
extrude "Extrude2" add sketch "Foot_6_6 sketch" against normal blind 3 (magnitude of "-( 3.0 mm )")
work_plane "WorkPlane3" AlongDistance -6.5 ExtraOffset 0
sketch "Leg_74_6 sketch" plane through (0, 0, -6.5) normal (0, 0, 1) x axis (1, 0, 0)
  circle C1 centre (74, 6) radius 4
extrude "Extrude3" new body sketch "Leg_74_6 sketch" against normal blind 16 (magnitude of "-( 16.0 mm )")
work_plane "WorkPlane4" AlongDistance -22.5 ExtraOffset 0
sketch "Foot_74_6 sketch" plane through (0, 0, -22.5) normal (0, 0, 1) x axis (1, 0, 0)
  circle C1 centre (74, 6) radius 6
extrude "Extrude4" add sketch "Foot_74_6 sketch" against normal blind 3 (magnitude of "-( 3.0 mm )")
work_plane "WorkPlane5" AlongDistance -6.5 ExtraOffset 0
sketch "Leg_6_114 sketch" plane through (0, 0, -6.5) normal (0, 0, 1) x axis (1, 0, 0)
  circle C1 centre (6, 114) radius 4
extrude "Extrude5" new body sketch "Leg_6_114 sketch" against normal blind 16 (magnitude of "-( 16.0 mm )")
work_plane "WorkPlane6" AlongDistance -22.5 ExtraOffset 0
sketch "Foot_6_114 sketch" plane through (0, 0, -22.5) normal (0, 0, 1) x axis (1, 0, 0)
  circle C1 centre (6, 114) radius 6
extrude "Extrude6" add sketch "Foot_6_114 sketch" against normal blind 3 (magnitude of "-( 3.0 mm )")
work_plane "WorkPlane7" AlongDistance -6.5 ExtraOffset 0
sketch "Leg_74_114 sketch" plane through (0, 0, -6.5) normal (0, 0, 1) x axis (1, 0, 0)
  circle C1 centre (74, 114) radius 4
extrude "Extrude7" new body sketch "Leg_74_114 sketch" against normal blind 16 (magnitude of "-( 16.0 mm )")
work_plane "WorkPlane8" AlongDistance -22.5 ExtraOffset 0
sketch "Foot_74_114 sketch" plane through (0, 0, -22.5) normal (0, 0, 1) x axis (1, 0, 0)
  circle C1 centre (74, 114) radius 6
extrude "Extrude8" add sketch "Foot_74_114 sketch" against normal blind 3 (magnitude of "-( 3.0 mm )")
position "Position1"
work_plane "WorkPlane13" AlongDistance 12 ExtraOffset 0
sketch "Sketch13" plane through (0, 0, 12) normal (0, 0, 1) x axis (1, 0, 0)
  circle C1 centre (40, 32) radius 2.1
  circle C2 centre (40, 88) radius 2.1
extrude "Extrude13" cut sketch "Sketch13" against normal blind 4 (magnitude of "-( 4.00 mm )")
position "Position2"
position "Position3"
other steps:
create_component "CreateComponent23"
create_component "CreateComponent24"
create_component "CreateComponent25"
create_component "CreateComponent26"
create_component "CreateComponent27"
extrude "Extrude2" cut sketch "Ring bore sketch" along normal blind 2.5
create_component "CreateComponent28"
create_component "CreateComponent29"
extrude "Extrude2" cut sketch "Ring bore sketch" along normal blind 2.5
create_component "CreateComponent30"
create_component "CreateComponent31"
create_component "CreateComponent32"
create_component "CreateComponent33"
create_component "CreateComponent34"
create_component "CreateComponent35"
create_component "CreateComponent36"
create_component "CreateComponent37"
create_component "CreateComponent38"
create_component "CreateComponent39"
